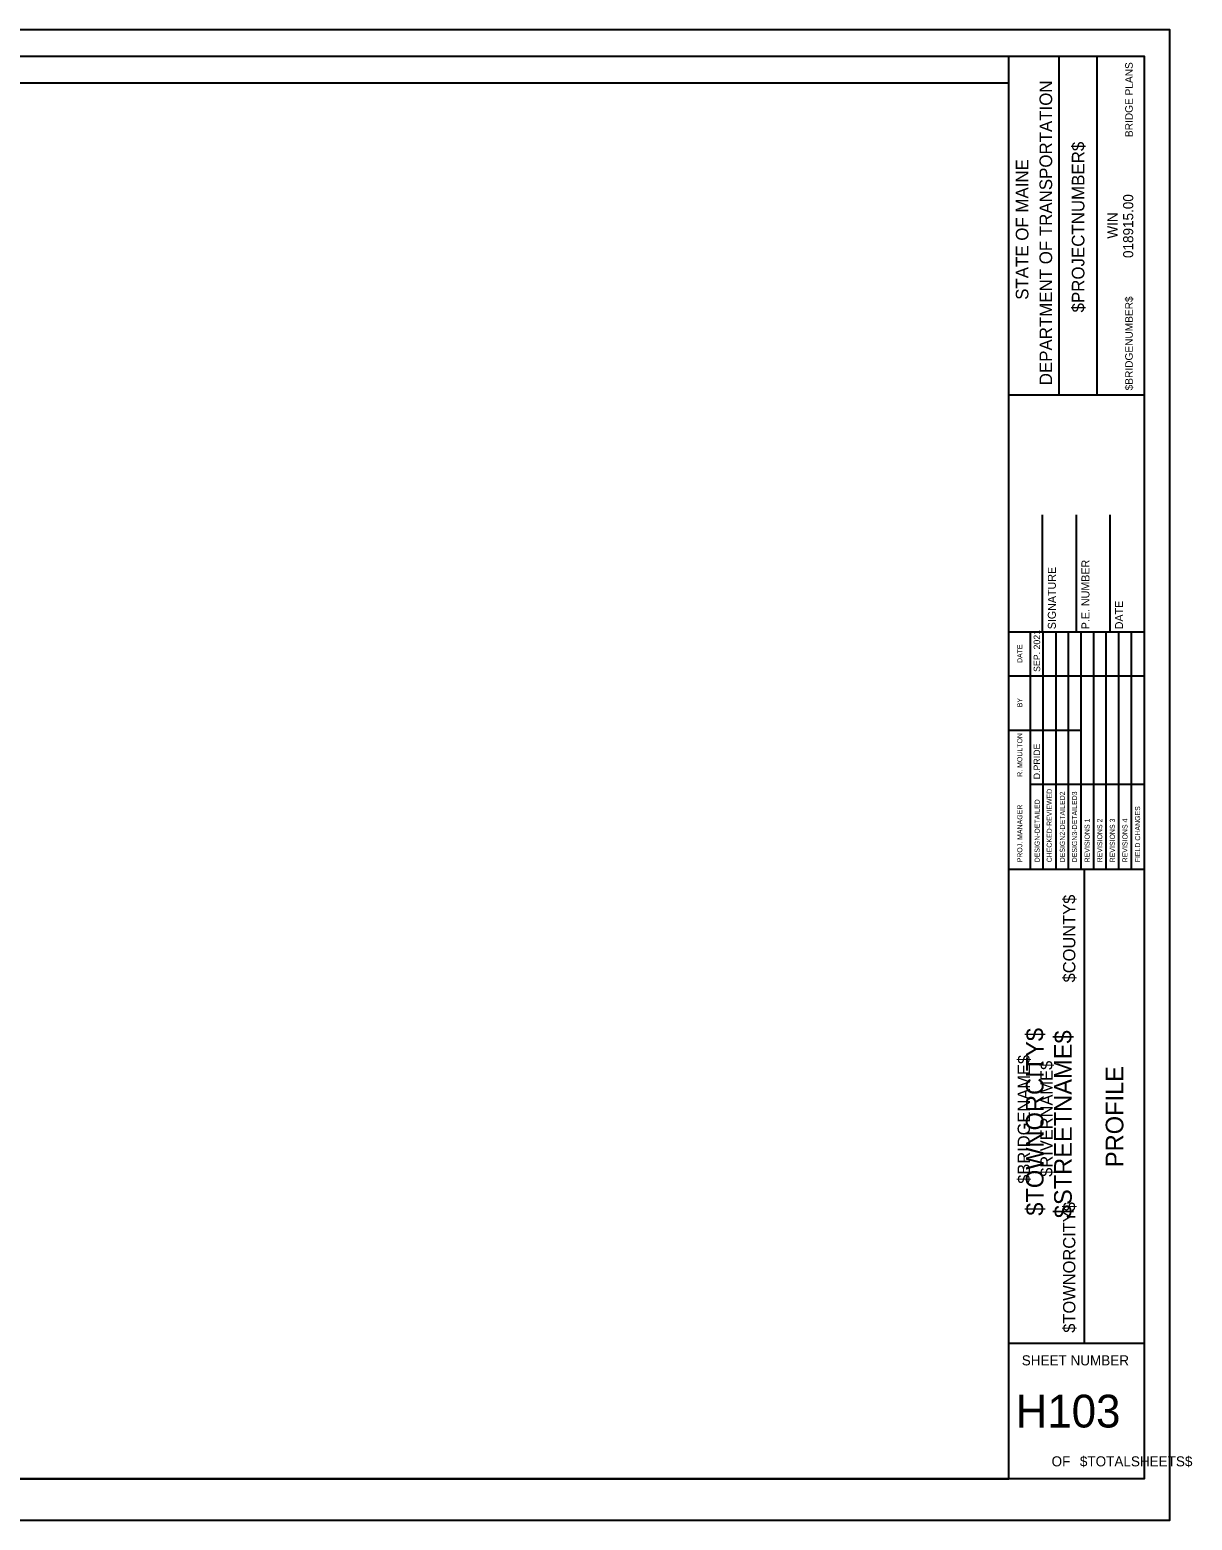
# Model space of a CAD drawing. Extents: x 34754 to 35612, y 9985 to 10535.
# Drawn here: x 35183 to 35612, y 9985 to 10535 of the extents above; entities that cross this region are included whole.
import ezdxf

# ---------------------------------------------------------------- set-up
doc = ezdxf.new("R2010")
doc.units = 0
for name, color, linetype in [('BORDER', 7, 'Continuous'), ('BRIDGE_TITLE', 7, 'Continuous'), ('CLIPS', 7, 'Continuous'), ('HIGHWAY_TITLE', 7, 'Continuous'), ('PLOT BOUNDARY', 7, 'Continuous')]:
    doc.layers.add(name, color=color, linetype=linetype)

msp = doc.modelspace()

# ---------------------------------------------------------------- linework, layer by layer
at = {"layer": 'BORDER'}
for p, q in [((35544.5, 10000), (35544.5, 10525)), ((35563.14, 10399.99), (35563.14, 10524.99)), ((35577.11, 10399.99), (35577.11, 10524.99)), ((35544.5, 10399.97), (35594.5, 10399.97)), ((35557, 10312.51), (35557, 10355.75)), ((35569.5, 10312.51), (35569.5, 10355.75)), ((35582, 10312.51), (35582, 10355.75)), ((35544.5, 10312.51), (35594.5, 10312.51)), ((35544.5, 10225.01), (35594.5, 10225.01)), ((35572.45, 10050.01), (35572.45, 10225.01)), ((35544.5, 10050.01), (35594.5, 10050.01))]:
    msp.add_line(p, q, dxfattribs=at)
msp.add_lwpolyline([(34794.5, 10525), (35594.5, 10525), (35594.5, 10000), (34794.5, 10000)], close=True, dxfattribs=at)
for points in [[(35552.57, 10296.26), (35552.57, 10312.51)], [(35557.23, 10225.03), (35557.23, 10312.51)], [(35561.89, 10312.51), (35561.89, 10225.03)], [(35566.55, 10225.03), (35566.55, 10312.51)], [(35571.21, 10225.03), (35571.21, 10312.51)], [(35575.87, 10225.03), (35575.87, 10312.51)], [(35580.52, 10225.03), (35580.52, 10312.51)], [(35585.18, 10225.03), (35585.18, 10312.51)], [(35589.84, 10225.03), (35589.84, 10312.51)], [(35552.57, 10225.03), (35552.57, 10308.98)], [(35544.5, 10296.26), (35594.5, 10296.26)], [(35544.5, 10276.26), (35552.57, 10276.26)], [(35552.57, 10276.26), (35571.2, 10276.26)], [(35552.57, 10256.26), (35594.5, 10256.26)]]:
    msp.add_lwpolyline(points, dxfattribs=at)
at = {"layer": 'CLIPS'}
msp.add_lwpolyline([(34794.5, 10000), (35544.5, 10000), (35544.5, 10515), (34794.5, 10515)], close=True, dxfattribs=at)
at = {"layer": 'PLOT BOUNDARY'}
msp.add_lwpolyline([(34754.03, 9984.7), (35604.03, 9984.7), (35604.03, 10534.7), (34754.03, 10534.7)], close=True, dxfattribs=at)

# ---------------------------------------------------------------- texts
at = {"layer": 'BORDER'}
for s, height, rotation, p in [('DEPARTMENT OF TRANSPORTATION', 4.6588, 90, (35560.53, 10403.53)), ('$PROJECTNUMBER$', 4.6588, 90, (35572.45, 10430.4)), ('STATE OF MAINE', 4.6588, 90, (35551.77, 10435.06)), ('018915.00', 3.726, 90, (35590.47, 10450.49)), ('WIN', 3.726, 90, (35584.68, 10457.65)), ('SIGNATURE', 2.953, 90, (35561.9, 10313.48)), ('P.E. NUMBER', 2.9528, 90, (35574.3, 10313.48)), ('DATE', 2.953, 90, (35586.7, 10313.48)), ('SEP. 2021', 2.423, 90, (35556.11, 10297.74)), ('DATE', 1.857, 90, (35549.52, 10301.04)), ('BY', 1.857, 90, (35549.52, 10284.69)), ('R. MOULTON', 1.864, 90, (35549.52, 10259.03)), ('D.PRIDE', 2.423, 90, (35556.11, 10258.13)), ('CHECKED-REVIEWED', 1.8637, 90, (35560.4, 10227.46)), ('DESIGN2-DETAILED2', 1.8637, 90, (35565.24, 10227.46)), ('DESIGN3-DETAILED3', 1.8637, 90, (35569.72, 10227.46)), ('PROJ. MANAGER', 1.8637, 90, (35549.52, 10227.46)), ('DESIGN-DETAILED', 1.8637, 90, (35555.93, 10227.46)), ('FIELD CHANGES', 1.8637, 90, (35593.01, 10227.46)), ('REVISIONS 1', 1.8637, 90, (35574.38, 10227.46)), ('REVISIONS 2', 1.8637, 90, (35579.03, 10227.46)), ('REVISIONS 3', 1.8637, 90, (35583.69, 10227.46)), ('REVISIONS 4', 1.8637, 90, (35588.35, 10227.46)), ('PROFILE', 6.521, 90, (35586.82, 10115)), ('SHEET NUMBER', 3.7264, 360, (35549.32, 10041.83)), ('H103', 12.097, 360, (35547.07, 10018.91)), ('OF', 3.726, 360, (35560.33, 10004.56)), ('$TOTALSHEETS$', 3.7264, 360, (35570.78, 10004.56))]:
    msp.add_text(s, height=height, rotation=rotation, dxfattribs=at).set_placement(p)
at = {"layer": 'BRIDGE_TITLE'}
for s, height, p in [('BRIDGE PLANS', 2.795, (35590.29, 10495.12)), ('$BRIDGENUMBER$', 2.795, (35590.29, 10401.65)), ('$COUNTY$', 4.536, (35569.1, 10183.17)), ('$BRIDGENAME$', 4.5358, (35552.33, 10108.86)), ('$RIVERNAME$', 4.5358, (35560.71, 10111.43)), ('$TOWNORCITY$', 4.5358, (35569.1, 10053.88))]:
    msp.add_text(s, height=height, rotation=90, dxfattribs=at).set_placement(p)
at = {"layer": 'HIGHWAY_TITLE'}
for s, p in [('$TOWNORCITY$', (35557.36, 10097.06)), ('$STREETNAME$', (35567.79, 10096.16))]:
    msp.add_text(s, height=6.5214, rotation=90, dxfattribs=at).set_placement(p)

doc.saveas('drawing.dxf')
